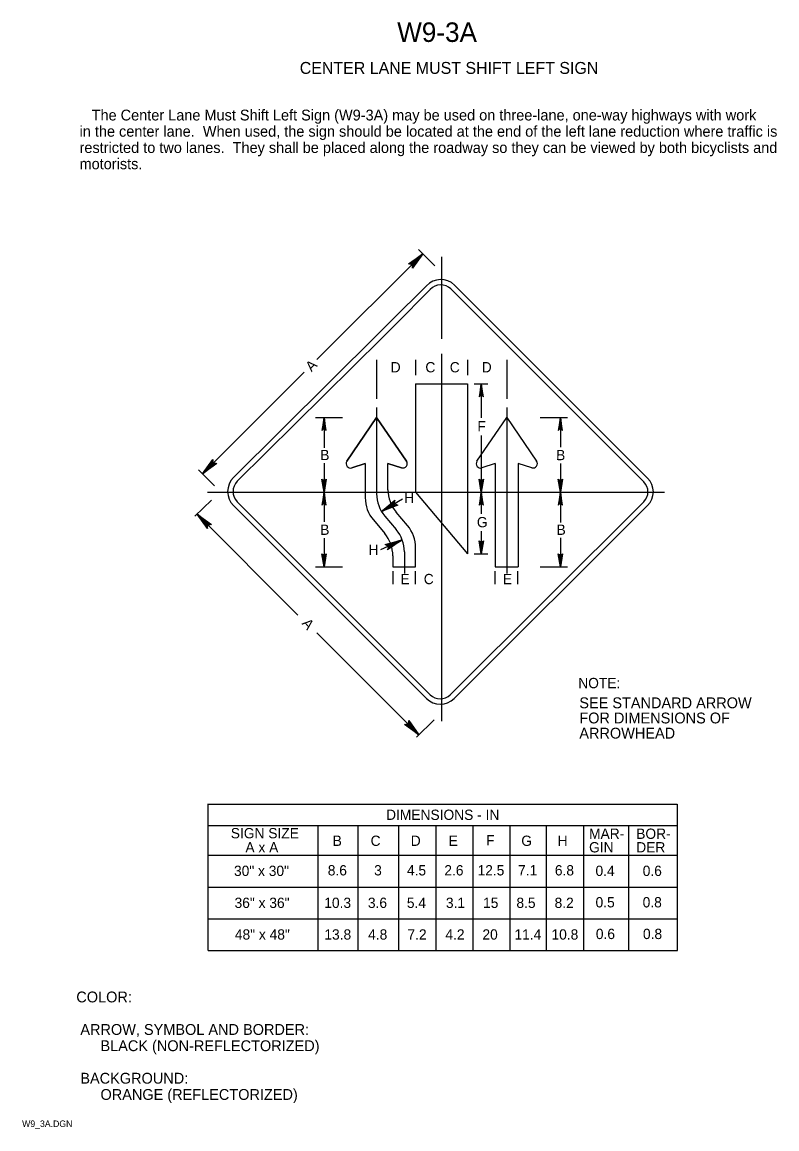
# Model space of a CAD drawing. Extents: x 0.013 to 0.187, y 0.004 to 0.259.
import ezdxf

# ---------------------------------------------------------------- set-up
doc = ezdxf.new("R2010")
doc.units = 0
for name, color, linetype in [('1', 7, 'Continuous'), ('2', 7, 'Continuous'), ('3', 7, 'Continuous')]:
    doc.layers.add(name, color=color, linetype=linetype)

# ---------------------------------------------------------------- blocks, each defined once
blk = doc.blocks.new('RARROW')
at = {"layer": '3'}
for p, q in [((-2.156, 0.28500000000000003), (-2.2665, 0.384625)), ((-2.2665, 0.384625), (0, 0)), ((0, 0), (-2.2665, -0.379125)), ((-2.156, 0.28500000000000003), (-2.075625, 0.12075)), ((0, 0), (-2.156, 0.28500000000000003)), ((-2.14975, -0.2705), (0, 0)), ((-2.075625, 0.12075), (0, 0)), ((0, 0), (-2.074, -0.108)), ((-2.2665, -0.379125), (-2.14975, -0.2705)), ((-2.074, -0.108), (-2.14975, -0.2705))]:
    blk.add_line(p, q, dxfattribs=at)

msp = doc.modelspace()

# ---------------------------------------------------------------- linework, layer by layer
at = {"layer": '1'}
for p, q in [((0.109375, 0.205125), (0.109375, 0.18625)), ((0.109375, 0.18275), (0.109375, 0.150875)), ((0.10337500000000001, 0.175875), (0.10337500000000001, 0.150875)), ((0.10337500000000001, 0.175875), (0.115375, 0.175875)), ((0.115375, 0.175875), (0.115375, 0.150875)), ((0.094375, 0.170375), (0.094375, 0.15051002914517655)), ((0.124375, 0.170375), (0.124375, 0.132125)), ((0.08752634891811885, 0.1579820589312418), (0.094375, 0.168125)), ((0.094375, 0.168125), (0.08752634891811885, 0.1579820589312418)), ((0.094375, 0.168125), (0.10127955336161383, 0.15802708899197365)), ((0.10127955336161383, 0.15802708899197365), (0.094375, 0.168125)), ((0.11752634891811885, 0.1579820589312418), (0.124375, 0.168125)), ((0.124375, 0.168125), (0.13127955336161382, 0.15802708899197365)), ((0.09175, 0.1575), (0.0886713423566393, 0.15647378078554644)), ((0.0886713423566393, 0.15647378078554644), (0.09175, 0.1575)), ((0.09175, 0.1575), (0.09175, 0.14959080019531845)), ((0.10015424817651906, 0.1565086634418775), (0.097, 0.1575)), ((0.097, 0.15142925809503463), (0.097, 0.1575)), ((0.097, 0.1575), (0.10015424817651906, 0.1565086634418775)), ((0.12175, 0.1575), (0.1186713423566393, 0.15647378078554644)), ((0.12175, 0.1575), (0.12175, 0.133625)), ((0.127, 0.1575), (0.127, 0.133625)), ((0.13015424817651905, 0.1565086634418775), (0.127, 0.1575)), ((0.055375, 0.150875), (0.16075, 0.150875)), ((0.10337500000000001, 0.150875), (0.115375, 0.136625)), ((0.109375, 0.150875), (0.109375, 0.098)), ((0.115375, 0.150875), (0.115375, 0.136625)), ((0.1014942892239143, 0.1431725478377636), (0.09888071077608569, 0.14627617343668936)), ((0.09363071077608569, 0.14443771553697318), (0.09624428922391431, 0.1413340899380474)), ((0.09625571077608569, 0.14535694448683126), (0.09889428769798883, 0.14222363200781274)), ((0.10337500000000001, 0.133625), (0.10337500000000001, 0.13801946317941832)), ((0.098125, 0.13618100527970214), (0.098125, 0.133625)), ((0.10077499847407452, 0.13707054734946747), (0.10077499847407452, 0.133625)), ((0.098125, 0.133625), (0.10337500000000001, 0.133625)), ((0.10077499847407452, 0.133625), (0.10077499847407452, 0.132125))]:
    msp.add_line(p, q, dxfattribs=at)
for centre, radius, start, end in [((0.08835511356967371, 0.1574224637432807), 0.001, 145.9722375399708, 288.43494612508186), ((0.08835511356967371, 0.1574224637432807), 0.001, 145.97224023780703, 288.43494882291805), ((0.10045407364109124, 0.15746265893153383), 0.001, 252.55281157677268, 34.362785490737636), ((0.10045407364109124, 0.15746265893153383), 0.001, 252.55281281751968, 34.36278673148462), ((0.11835511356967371, 0.1574224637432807), 0.001, 145.9722375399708, 288.43494612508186), ((0.13045407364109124, 0.15746265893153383), 0.001, 252.55281157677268, 34.362785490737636), ((0.105, 0.15142925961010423), 0.008, 180, 220.10089871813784), ((0.09975, 0.14959080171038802), 0.008, 180.00000256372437, 220.1009012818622), ((0.10237500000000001, 0.15051003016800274), 0.008, 180, 220.10089249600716), ((0.095375, 0.13801946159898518), 0.008, 0, 40.1008995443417), ((0.090125, 0.1361810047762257), 0.008, 0, 40.10090524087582), ((0.09277499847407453, 0.13707054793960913), 0.008, 360, 40.10090473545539)]:
    msp.add_arc(centre, radius, start, end, dxfattribs=at)
at = {"layer": '3'}
for p, q in [((0.105, 0.205875), (0.08057712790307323, 0.18145212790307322)), ((0.10777809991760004, 0.20311770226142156), (0.10407488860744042, 0.20682091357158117)), ((0.105875, 0.1985), (0.09775, 0.19037500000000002)), ((0.10675, 0.197625), (0.098625, 0.1895)), ((0.156, 0.15325), (0.1115, 0.19775)), ((0.15687500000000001, 0.154125), (0.112375, 0.198625)), ((0.09775, 0.19037500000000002), (0.09475, 0.187375)), ((0.098625, 0.1895), (0.095625, 0.1865)), ((0.109375, 0.18912500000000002), (0.109375, 0.18625)), ((0.09475, 0.187375), (0.061375, 0.15425)), ((0.095625, 0.1865), (0.06225, 0.153375)), ((0.094375, 0.181375), (0.094375, 0.172375)), ((0.10337500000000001, 0.181375), (0.10337500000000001, 0.177875)), ((0.115375, 0.181375), (0.115375, 0.177875)), ((0.124375, 0.181375), (0.124375, 0.172375)), ((0.07766030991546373, 0.17853530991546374), (0.05425, 0.155125)), ((0.116875, 0.175875), (0.12, 0.175875)), ((0.11850000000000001, 0.175875), (0.11850000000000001, 0.168)), ((0.08025, 0.168125), (0.08650000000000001, 0.168125)), ((0.08225, 0.168125), (0.08225, 0.161125)), ((0.132125, 0.168125), (0.138375, 0.168125)), ((0.13675, 0.168125), (0.13675, 0.16125)), ((0.11850000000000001, 0.16396441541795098), (0.11850000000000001, 0.150875)), ((0.05699431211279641, 0.152345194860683), (0.0532911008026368, 0.15604840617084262)), ((0.08225, 0.15754425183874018), (0.08225, 0.150875)), ((0.13675, 0.1574498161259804), (0.13675, 0.150875)), ((0.08225, 0.150875), (0.08225, 0.14400000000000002)), ((0.11850000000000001, 0.150875), (0.11850000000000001, 0.145875)), ((0.13675, 0.150875), (0.13675, 0.143875)), ((0.05626771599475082, 0.14902496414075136), (0.05248402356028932, 0.14530650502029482)), ((0.06225, 0.148625), (0.10675, 0.104125)), ((0.10031105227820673, 0.14926414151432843), (0.0955, 0.146375)), ((0.111375, 0.104125), (0.156, 0.148625)), ((0.07618279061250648, 0.12244257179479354), (0.053, 0.14575)), ((0.061375, 0.14775), (0.105875, 0.10325000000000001)), ((0.11225, 0.10325000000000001), (0.15687500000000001, 0.14775)), ((0.11850000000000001, 0.14183546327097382), (0.11850000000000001, 0.136625)), ((0.08225, 0.14021988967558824), (0.08225, 0.133625)), ((0.095375, 0.137625), (0.10025, 0.139875)), ((0.13675, 0.14033606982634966), (0.13675, 0.133625)), ((0.116875, 0.136625), (0.12, 0.136625)), ((0.08025, 0.133625), (0.08650000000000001, 0.133625)), ((0.12175, 0.133625), (0.127, 0.133625)), ((0.132125, 0.133625), (0.138375, 0.133625)), ((0.09817500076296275, 0.129625), (0.09817500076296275, 0.132625)), ((0.10337500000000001, 0.129625), (0.10337500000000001, 0.132625)), ((0.12175, 0.129625), (0.12175, 0.132625)), ((0.12694999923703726, 0.129625), (0.12694999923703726, 0.132625)), ((0.080625, 0.11837500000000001), (0.104125, 0.094875)), ((0.10763574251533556, 0.0983453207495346), (0.10358285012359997, 0.09429242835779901)), ((0.055372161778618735, 0.07887768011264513), (0.1636933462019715, 0.07887768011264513)), ((0.05544334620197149, 0.07887768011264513), (0.05544334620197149, 0.045106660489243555)), ((0.1636933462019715, 0.07887768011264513), (0.1636933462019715, 0.045106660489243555)), ((0.1636933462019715, 0.07386158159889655), (0.055372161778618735, 0.07386158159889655)), ((0.08083583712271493, 0.07386158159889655), (0.08083583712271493, 0.045106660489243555)), ((0.0900683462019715, 0.07386158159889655), (0.0900683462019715, 0.045106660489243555)), ((0.0994433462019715, 0.07386158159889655), (0.0994433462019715, 0.045106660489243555)), ((0.10806834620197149, 0.07386158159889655), (0.10806834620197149, 0.045106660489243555)), ((0.1165683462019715, 0.07386158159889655), (0.1165683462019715, 0.045106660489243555)), ((0.1250683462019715, 0.07386158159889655), (0.1250683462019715, 0.045106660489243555)), ((0.1334433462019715, 0.07386158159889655), (0.1334433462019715, 0.045106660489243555)), ((0.1420683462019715, 0.07386158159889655), (0.1420683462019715, 0.045106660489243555)), ((0.152442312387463, 0.07386158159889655), (0.152442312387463, 0.045106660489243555)), ((0.055372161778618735, 0.06709033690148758), (0.1636933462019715, 0.06709033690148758)), ((0.055372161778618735, 0.05971533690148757), (0.1636933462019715, 0.05971533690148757)), ((0.05544334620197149, 0.052410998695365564), (0.1636933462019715, 0.052410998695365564)), ((0.05551453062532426, 0.045106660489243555), (0.16376453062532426, 0.045106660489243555))]:
    msp.add_line(p, q, dxfattribs=at)
for centre, radius, start, end in [((0.1091875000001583, 0.19531249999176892), 0.004597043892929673, 46.10170555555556, 136.10170555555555), ((0.10918749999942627, 0.19531250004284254), 0.0033599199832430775, 46.50743611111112, 136.50743611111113), ((0.06462500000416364, 0.15099999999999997), 0.004596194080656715, 135, 225), ((0.06462499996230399, 0.1509999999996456), 0.0033587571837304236, 135, 225), ((0.1536875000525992, 0.15093749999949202), 0.003270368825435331, 315, 45), ((0.15368750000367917, 0.1509375), 0.0045078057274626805, 315, 45), ((0.10906250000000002, 0.10643750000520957), 0.004507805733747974, 225.00000000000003, 315), ((0.10906250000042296, 0.1064374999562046), 0.0032703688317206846, 225.00000000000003, 315)]:
    msp.add_arc(centre, radius, start, end, dxfattribs=at)

# ---------------------------------------------------------------- block references
for p, xscale, yscale, rotation in [((0.105, 0.205875), 0.001764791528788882, 0.0017457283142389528, 44.99999999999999), ((0.11850000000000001, 0.175875), 0.0013235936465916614, -0.0013092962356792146, 90.00000000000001), ((0.08225, 0.168125), 0.0013235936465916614, -0.0013092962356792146, 90.00000000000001), ((0.13675, 0.168125), 0.0013235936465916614, -0.0013092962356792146, 90.00000000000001), ((0.05425, 0.155125), 0.001764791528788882, 0.0017457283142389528, -135.00000000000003), ((0.08225, 0.150875), 0.0013235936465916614, 0.0013092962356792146, -90.00000000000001), ((0.11850000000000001, 0.150875), 0.0013235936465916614, 0.0013092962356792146, -90.00000000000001), ((0.13675, 0.150875), 0.0013235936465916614, 0.0013092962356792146, -90.00000000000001), ((0.08225, 0.150875), 0.0013235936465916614, -0.0013092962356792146, 90.00000000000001), ((0.11850000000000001, 0.150875), 0.0013235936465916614, -0.0013092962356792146, 90.00000000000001), ((0.13675, 0.150875), 0.0013235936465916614, -0.0013092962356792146, 90.00000000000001), ((0.0955, 0.146375), 0.0017647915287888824, 0.0017457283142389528, -148.99999999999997), ((0.053, 0.14575), 0.001764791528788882, 0.0017457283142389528, 135), ((0.10025, 0.139875), 0.0017647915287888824, 0.0017457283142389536, 25.000000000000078), ((0.11850000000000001, 0.136625), 0.0013235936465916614, 0.0013092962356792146, -90.00000000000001), ((0.08225, 0.133625), 0.0013235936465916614, 0.0013092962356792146, -90.00000000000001), ((0.13675, 0.133625), 0.0013235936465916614, 0.0013092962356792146, -90.00000000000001), ((0.104125, 0.094875), 0.001764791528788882, 0.0017457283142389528, -45.00000000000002)]:
    msp.add_blockref('RARROW', p, dxfattribs=dict(at, xscale=xscale, yscale=yscale, rotation=rotation))

# ---------------------------------------------------------------- texts
at = {"layer": '1'}
for s, height, p in [('W9-3A', 0.0045000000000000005, (0.099125, 0.25475000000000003)), ('CENTER LANE MUST SHIFT LEFT SIGN', 0.00275025, (0.07665080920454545, 0.247375)), ('NOTE:', 0.0023752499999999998, (0.140875, 0.105625)), ('SEE STANDARD ARROW', 0.0024997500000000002, (0.141125, 0.101)), ('FOR DIMENSIONS OF', 0.0024997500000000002, (0.141125, 0.0975)), ('ARROWHEAD', 0.0024997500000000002, (0.141125, 0.094)), ('COLOR:', 0.0024997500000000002, (0.025125, 0.033124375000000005)), (' ARROW, SYMBOL AND BORDER:', 0.0024997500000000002, (0.025125, 0.025624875)), ('      BLACK (NON-REFLECTORIZED)', 0.0024997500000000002, (0.025125, 0.021875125)), (' BACKGROUND:', 0.0024997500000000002, (0.025125, 0.014375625)), ('      ORANGE (REFLECTORIZED)', 0.0024997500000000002, (0.025125, 0.010625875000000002)), ('W9_3A.DGN', 0.0015, (0.012625, 0.004375))]:
    msp.add_text(s, height=height, dxfattribs=at).set_placement(p)
at = {"layer": '2'}
for s, p in [('   The Center Lane Must Shift Left Sign (W9-3A) may be used on three-lane, one-way highways with work', (0.025875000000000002, 0.236625)), ('in the center lane.  When used, the sign should be located at the end of the left lane reduction where traffic is ', (0.025875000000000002, 0.232875)), ('restricted to two lanes.  They shall be placed along the roadway so they can be viewed by both bicyclists and', (0.025875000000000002, 0.229125)), ('motorists.', (0.025875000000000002, 0.225375))]:
    msp.add_text(s, height=0.0024997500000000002, dxfattribs=at).set_placement(p)
at = {"layer": '3'}
for s, height, rotation, p in [('A', 0.0023752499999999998, 45, (0.079375, 0.1785)), ('B', 0.0023737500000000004, 359, (0.13575, 0.15825)), ('A', 0.0023745, 310.46116111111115, (0.077, 0.1205))]:
    msp.add_text(s, height=height, rotation=rotation, dxfattribs=at).set_placement(p)
for s, height, p in [('D', 0.0023752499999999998, (0.097625, 0.1785)), ('C', 0.0023752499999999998, (0.105625, 0.1785)), ('C', 0.0023752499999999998, (0.11125, 0.1785)), ('D', 0.0023752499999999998, (0.11862500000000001, 0.1785)), ('F', 0.0023737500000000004, (0.11762500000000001, 0.164875)), ('B', 0.0023752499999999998, (0.081375, 0.15825)), ('H', 0.0023745, (0.10075, 0.148375)), ('B', 0.0023752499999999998, (0.081375, 0.14100000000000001)), ('G', 0.0023737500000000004, (0.11750000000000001, 0.14275000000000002)), ('B', 0.0023752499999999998, (0.135875, 0.14100000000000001)), ('H', 0.0023745, (0.0925, 0.136375)), ('E', 0.0023737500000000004, (0.099875, 0.129625)), ('C', 0.0023737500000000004, (0.10525, 0.129625)), ('E', 0.0023737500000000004, (0.1235, 0.129625)), ('DIMENSIONS - IN', 0.0023752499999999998, (0.09656659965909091, 0.07523154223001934)), ('SIGN SIZE', 0.0023752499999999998, (0.06075, 0.07098154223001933)), ('B', 0.0023752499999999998, (0.08425, 0.06923154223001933)), ('C', 0.0023752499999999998, (0.093, 0.06923154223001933)), ('D', 0.0023752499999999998, (0.10225000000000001, 0.06923154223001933)), ('E', 0.0023752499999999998, (0.111, 0.06923154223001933)), ('F', 0.0023752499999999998, (0.11962500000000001, 0.06935654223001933)), ('G', 0.0023752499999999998, (0.12775, 0.06923154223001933)), ('H', 0.0023752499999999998, (0.136125, 0.06923154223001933)), ('MAR-', 0.0023752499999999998, (0.143375, 0.07085654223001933)), ('BOR-', 0.0023752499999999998, (0.15425, 0.07085654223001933)), ('A x A', 0.0023752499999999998, (0.064125, 0.06773154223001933)), ('GIN', 0.0023752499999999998, (0.143375, 0.06773154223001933)), ('DER', 0.0023752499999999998, (0.15425, 0.06773154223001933)), ('30" x 30"', 0.0023752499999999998, (0.06149541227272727, 0.062293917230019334)), ('8.6', 0.0023752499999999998, (0.08311851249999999, 0.062418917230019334)), ('3', 0.0023752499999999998, (0.09380661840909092, 0.062418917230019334)), ('4.5', 0.0023752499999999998, (0.1013713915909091, 0.062418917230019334)), ('2.6', 0.0023752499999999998, (0.1099935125, 0.062418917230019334)), ('12.5', 0.0023752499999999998, (0.11765161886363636, 0.062418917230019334)), ('7.1', 0.0023752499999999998, (0.12699039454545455, 0.062418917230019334)), ('6.8', 0.0023752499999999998, (0.1354805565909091, 0.062418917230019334)), ('0.4', 0.0023752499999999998, (0.14485699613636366, 0.062293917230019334)), ('0.6', 0.0023752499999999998, (0.15574351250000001, 0.062293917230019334)), ('36" x 36"', 0.0023752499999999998, (0.06162041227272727, 0.054918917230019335)), ('10.3', 0.0023752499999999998, (0.08230828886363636, 0.054918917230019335)), ('3.6', 0.0023752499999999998, (0.0923685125, 0.054918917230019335)), ('5.4', 0.0023752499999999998, (0.10135699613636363, 0.054918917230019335)), ('3.1', 0.0023752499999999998, (0.11036539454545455, 0.054918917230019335)), ('15', 0.0023752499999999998, (0.11893017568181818, 0.054918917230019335)), ('8.5', 0.0023752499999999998, (0.1266213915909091, 0.054918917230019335)), ('8.2', 0.0023752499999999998, (0.13541997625, 0.054918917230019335)), ('0.5', 0.0023752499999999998, (0.14487139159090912, 0.055043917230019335)), ('0.8', 0.0023752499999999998, (0.1557305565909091, 0.055043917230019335)), ('48" x 48"', 0.0023752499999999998, (0.061691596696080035, 0.04761457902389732)), ('13.8', 0.0023752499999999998, (0.08233196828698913, 0.04761457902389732)), ('4.8', 0.0023752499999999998, (0.09242674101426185, 0.04761457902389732)), ('7.2', 0.0023752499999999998, (0.10149116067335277, 0.04761457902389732)), ('4.2', 0.0023752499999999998, (0.11024116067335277, 0.04761457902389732)), ('20', 0.0023752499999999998, (0.11877751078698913, 0.04761457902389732)), ('11.4', 0.0023752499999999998, (0.1261743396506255, 0.04761457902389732)), ('10.8', 0.0023752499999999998, (0.13470696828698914, 0.04761457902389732)), ('0.6', 0.0023752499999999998, (0.14493969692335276, 0.04773957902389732)), ('0.8', 0.0023752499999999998, (0.15580174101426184, 0.04773957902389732))]:
    msp.add_text(s, height=height, dxfattribs=at).set_placement(p)

doc.saveas('drawing.dxf')
